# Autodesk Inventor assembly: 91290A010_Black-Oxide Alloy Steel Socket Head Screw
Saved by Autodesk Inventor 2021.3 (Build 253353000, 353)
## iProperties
Created: 2022-04
Part Number: 91290A010_Black-Oxide Alloy Steel Socket Head Screw
Document SubType Name: Assembly
Designer: Administrator
Title: 91290A010_Black-Oxide Alloy Steel Socket Head Screw v2
Author: Administrator
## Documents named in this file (2)
- c:\worker\convert-fusion-r02\tmp\job-1\960\output\files\e4e9fc01-2be7-40cb-83d9-200665603a36\5707d131-0582-41cb-913a-3cf647a36c24.iam
- c:\worker\convert-fusion-r02\tmp\job-1\960\output\files\e4e9fc01-2be7-40cb-83d9-200665603a36\Component1.ipt
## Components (1 placed, 1 different names)
1. Component1:1
